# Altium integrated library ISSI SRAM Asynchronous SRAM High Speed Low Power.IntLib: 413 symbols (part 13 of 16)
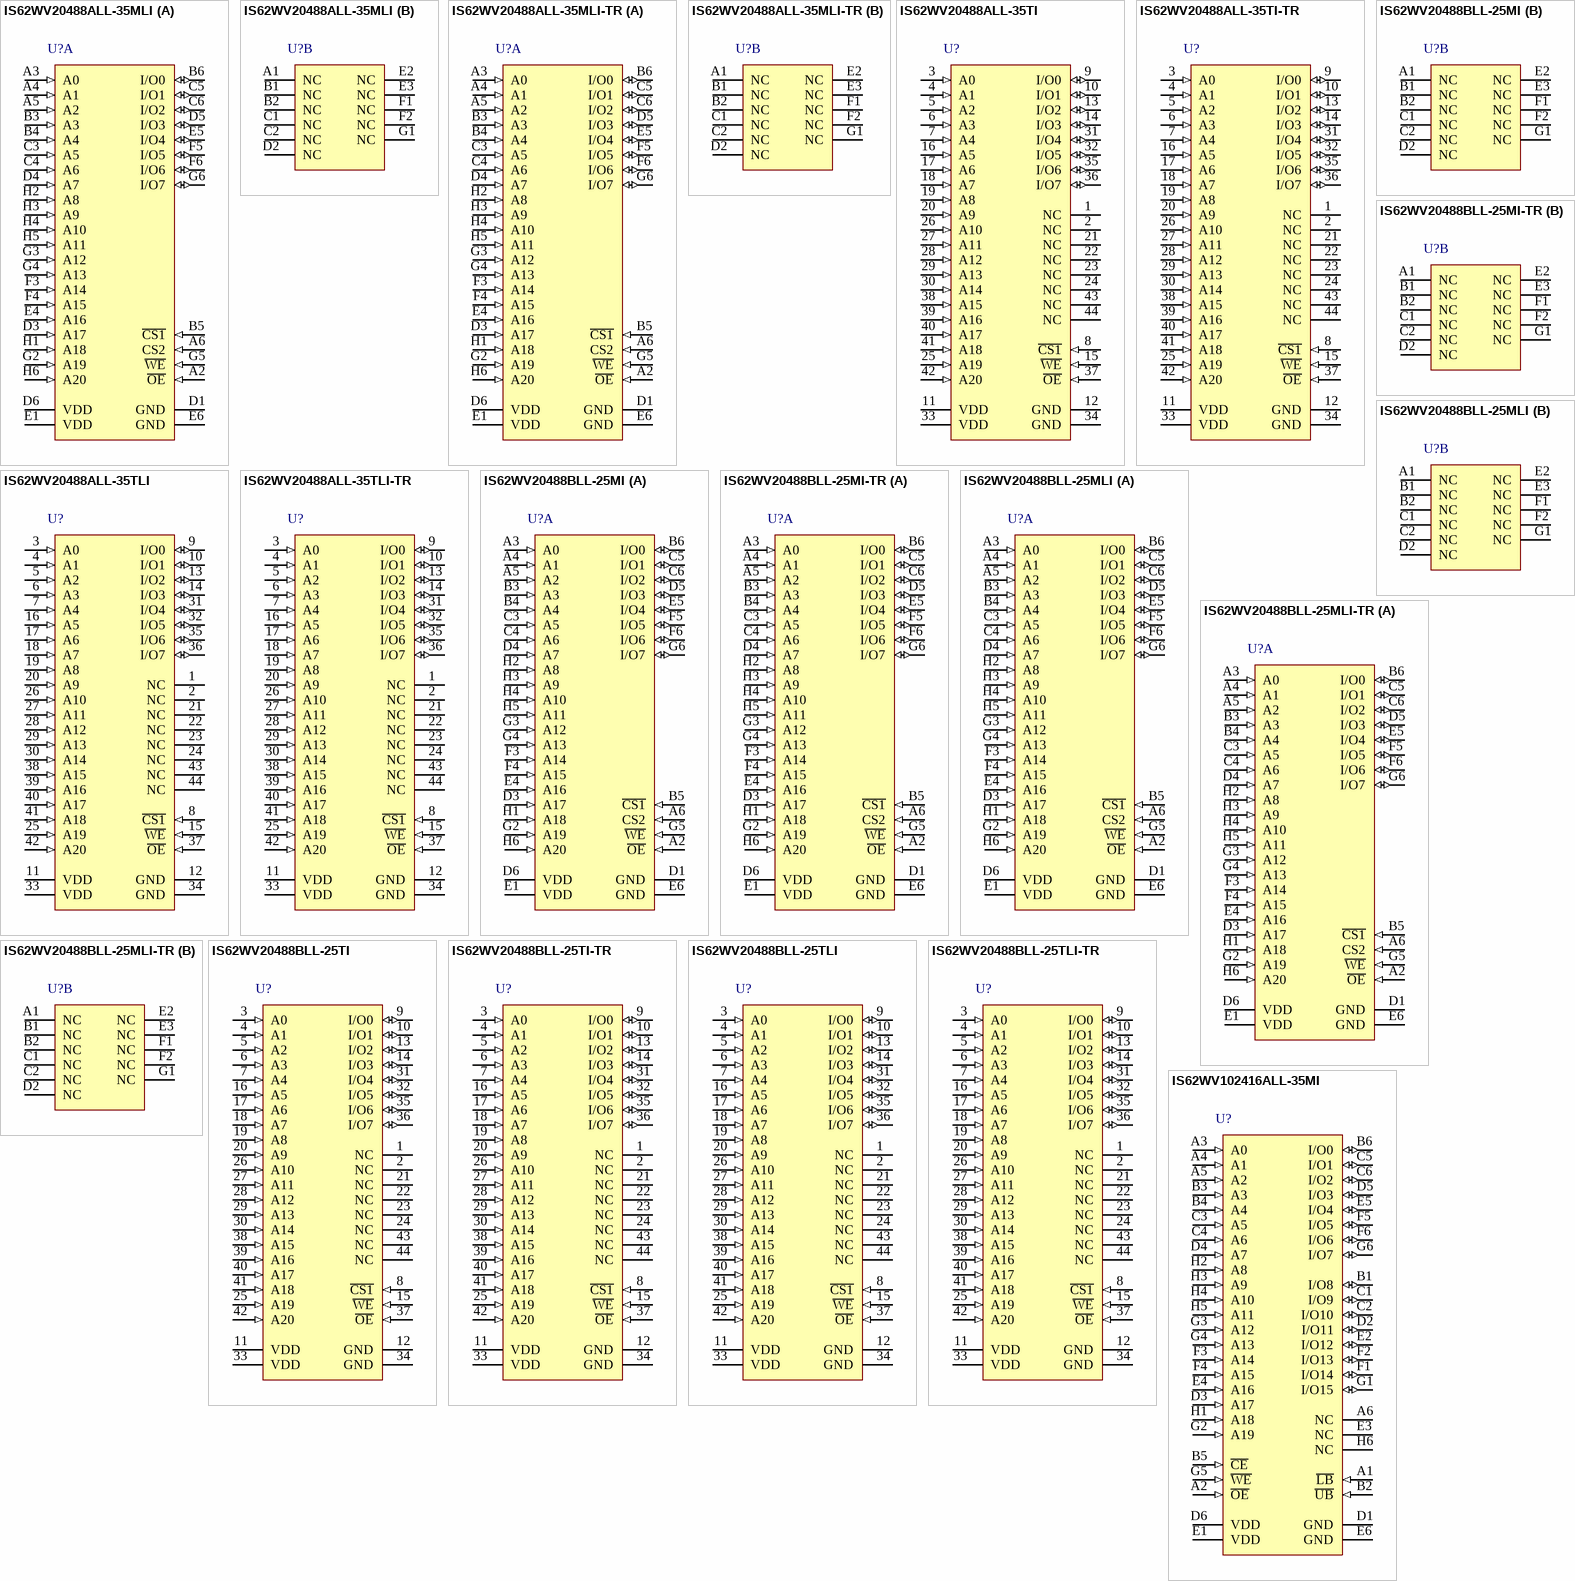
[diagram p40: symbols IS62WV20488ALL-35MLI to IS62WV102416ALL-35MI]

## IS62WV20488BLL-25MLI-TR
designator U?
16 M High Speed Low Power CMOS SRAM, 2 M x 8, -40 to 85 degC, 48-Pin BGA (TF-BGA-48), Pb-Free; Manufacturer: Integrated Silicon Solution Inc (ISSI); PartNumber: IS62WV20488BLL-25MLI-TR; Density: 16M; Organization: 2M x 8; Packing: Tape & Reel; Speed (ns): 25
footprint ISSI-TF-BGA-48-9000x11000DE (BGA, 48-Balls, Body 11x9mm, Pitch 0.75mm)
part A pins: A2 ~{OE} (in) "Output Enable Input", A3 A0 (in) "Address Input", A4 A1 (in) "Address Input", A5 A2 (in) "Address Input", A6 CS2 (in) "Chip Enable Input", B3 A3 (in) "Address Input", B4 A4 (in) "Address Input", B5 ~{CS1} (in) "Chip Enable Input", B6 I/O0 (io) "Data Input / Output", C3 A5 (in) "Address Input", C4 A6 (in) "Address Input", C5 I/O1 (io) "Data Input / Output", C6 I/O2 (io) "Data Input / Output", D1 GND (power) "Ground", D3 A17 (in) "Address Input", D4 A7 (in) "Address Input", D5 I/O3 (io) "Data Input / Output", D6 VDD (power) "Power", E1 VDD (power) "Power", E4 A16 (in) "Address Input", E5 I/O4 (io) "Data Input / Output", E6 GND (power) "Ground", F3 A14 (in) "Address Input", F4 A15 (in) "Address Input", F5 I/O5 (io) "Data Input / Output", F6 I/O6 (io) "Data Input / Output", G2 A19 (in) "Address Input", G3 A12 (in) "Address Input", G4 A13 (in) "Address Input", G5 ~{WE} (in) "Write Enable Input", G6 I/O7 (io) "Data Input / Output", H1 A18 (in) "Address Input", H2 A8 (in) "Address Input", H3 A9 (in) "Address Input", H4 A10 (in) "Address Input", H5 A11 (in) "Address Input", H6 A20 (in) "Address Input"
part B pins: A1 NC "No Connection", B1 NC "No Connection", B2 NC "No Connection", C1 NC "No Connection", C2 NC "No Connection", D2 NC "No Connection", E2 NC "No Connection", E3 NC "No Connection", F1 NC "No Connection", F2 NC "No Connection", G1 NC "No Connection"

## IS62WV20488BLL-25TI
designator U?
16 M High Speed Low Power CMOS SRAM, 2 M x 8, -40 to 85 degC, 44-Pin SOP (TSOP-2-44); Manufacturer: Integrated Silicon Solution Inc (ISSI); PartNumber: IS62WV20488BLL-25TI; Density: 16M; Organization: 2M x 8; Packing: Tray / Tube; Speed (ns): 25
footprint ISSI-TSOP-2-44_N (SOP, 44-Leads, Body 18.5x10.3mm, Pitch 0.8mm, IPC Medium Density)
pins: 1 NC "No Connection", 2 NC "No Connection", 3 A0 (in) "Address Inputs", 4 A1 (in) "Address Inputs", 5 A2 (in) "Address Inputs", 6 A3 (in) "Address Inputs", 7 A4 (in) "Address Inputs", 8 ~{CS1} (in) "Chip Enable Input", 9 I/O0 (io) "Data Input / Output", 10 I/O1 (io) "Data Input / Output", 11 VDD (power) "Power", 12 GND (power) "Ground", 13 I/O2 (io) "Data Input / Output", 14 I/O3 (io) "Data Input / Output", 15 ~{WE} (in) "Write Enable Input", 16 A5 (in) "Address Inputs", 17 A6 (in) "Address Inputs", 18 A7 (in) "Address Inputs", 19 A8 (in) "Address Inputs", 20 A9 (in) "Address Inputs", 21 NC "No Connection", 22 NC "No Connection", 23 NC "No Connection", 24 NC "No Connection", 25 A19 (in) "Address Inputs", 26 A10 (in) "Address Inputs", 27 A11 (in) "Address Inputs", 28 A12 (in) "Address Inputs", 29 A13 (in) "Address Inputs", 30 A14 (in) "Address Inputs", 31 I/O4 (io) "Data Input / Output", 32 I/O5 (io) "Data Input / Output", 33 VDD (power) "Power", 34 GND (power) "Ground", 35 I/O6 (io) "Data Input / Output", 36 I/O7 (io) "Data Input / Output", 37 ~{OE} (in) "Output Enable Input", 38 A15 (in) "Address Inputs", 39 A16 (in) "Address Inputs", 40 A17 (in) "Address Inputs", 41 A18 (in) "Address Inputs", 42 A20 (in) "Address Inputs", 43 NC "No Connection", 44 NC "No Connection"

## IS62WV20488BLL-25TI-TR
designator U?
16 M High Speed Low Power CMOS SRAM, 2 M x 8, -40 to 85 degC, 44-Pin SOP (TSOP-2-44); Manufacturer: Integrated Silicon Solution Inc (ISSI); PartNumber: IS62WV20488BLL-25TI-TR; Density: 16M; Organization: 2M x 8; Packing: Tape & Reel; Speed (ns): 25
footprint ISSI-TSOP-2-44_N (SOP, 44-Leads, Body 18.5x10.3mm, Pitch 0.8mm, IPC Medium Density)
pins: 1 NC "No Connection", 2 NC "No Connection", 3 A0 (in) "Address Inputs", 4 A1 (in) "Address Inputs", 5 A2 (in) "Address Inputs", 6 A3 (in) "Address Inputs", 7 A4 (in) "Address Inputs", 8 ~{CS1} (in) "Chip Enable Input", 9 I/O0 (io) "Data Input / Output", 10 I/O1 (io) "Data Input / Output", 11 VDD (power) "Power", 12 GND (power) "Ground", 13 I/O2 (io) "Data Input / Output", 14 I/O3 (io) "Data Input / Output", 15 ~{WE} (in) "Write Enable Input", 16 A5 (in) "Address Inputs", 17 A6 (in) "Address Inputs", 18 A7 (in) "Address Inputs", 19 A8 (in) "Address Inputs", 20 A9 (in) "Address Inputs", 21 NC "No Connection", 22 NC "No Connection", 23 NC "No Connection", 24 NC "No Connection", 25 A19 (in) "Address Inputs", 26 A10 (in) "Address Inputs", 27 A11 (in) "Address Inputs", 28 A12 (in) "Address Inputs", 29 A13 (in) "Address Inputs", 30 A14 (in) "Address Inputs", 31 I/O4 (io) "Data Input / Output", 32 I/O5 (io) "Data Input / Output", 33 VDD (power) "Power", 34 GND (power) "Ground", 35 I/O6 (io) "Data Input / Output", 36 I/O7 (io) "Data Input / Output", 37 ~{OE} (in) "Output Enable Input", 38 A15 (in) "Address Inputs", 39 A16 (in) "Address Inputs", 40 A17 (in) "Address Inputs", 41 A18 (in) "Address Inputs", 42 A20 (in) "Address Inputs", 43 NC "No Connection", 44 NC "No Connection"

## IS62WV20488BLL-25TLI
designator U?
16 M High Speed Low Power CMOS SRAM, 2 M x 8, -40 to 85 degC, 44-Pin SOP (TSOP-2-44), Pb-Free; Manufacturer: Integrated Silicon Solution Inc (ISSI); PartNumber: IS62WV20488BLL-25TLI; Density: 16M; Organization: 2M x 8; Packing: Tray / Tube; Speed (ns): 25
footprint ISSI-TSOP-2-44_N (SOP, 44-Leads, Body 18.5x10.3mm, Pitch 0.8mm, IPC Medium Density)
pins: 1 NC "No Connection", 2 NC "No Connection", 3 A0 (in) "Address Inputs", 4 A1 (in) "Address Inputs", 5 A2 (in) "Address Inputs", 6 A3 (in) "Address Inputs", 7 A4 (in) "Address Inputs", 8 ~{CS1} (in) "Chip Enable Input", 9 I/O0 (io) "Data Input / Output", 10 I/O1 (io) "Data Input / Output", 11 VDD (power) "Power", 12 GND (power) "Ground", 13 I/O2 (io) "Data Input / Output", 14 I/O3 (io) "Data Input / Output", 15 ~{WE} (in) "Write Enable Input", 16 A5 (in) "Address Inputs", 17 A6 (in) "Address Inputs", 18 A7 (in) "Address Inputs", 19 A8 (in) "Address Inputs", 20 A9 (in) "Address Inputs", 21 NC "No Connection", 22 NC "No Connection", 23 NC "No Connection", 24 NC "No Connection", 25 A19 (in) "Address Inputs", 26 A10 (in) "Address Inputs", 27 A11 (in) "Address Inputs", 28 A12 (in) "Address Inputs", 29 A13 (in) "Address Inputs", 30 A14 (in) "Address Inputs", 31 I/O4 (io) "Data Input / Output", 32 I/O5 (io) "Data Input / Output", 33 VDD (power) "Power", 34 GND (power) "Ground", 35 I/O6 (io) "Data Input / Output", 36 I/O7 (io) "Data Input / Output", 37 ~{OE} (in) "Output Enable Input", 38 A15 (in) "Address Inputs", 39 A16 (in) "Address Inputs", 40 A17 (in) "Address Inputs", 41 A18 (in) "Address Inputs", 42 A20 (in) "Address Inputs", 43 NC "No Connection", 44 NC "No Connection"

## IS62WV20488BLL-25TLI-TR
designator U?
16 M High Speed Low Power CMOS SRAM, 2 M x 8, -40 to 85 degC, 44-Pin SOP (TSOP-2-44), Pb-Free; Manufacturer: Integrated Silicon Solution Inc (ISSI); PartNumber: IS62WV20488BLL-25TLI-TR; Density: 16M; Organization: 2M x 8; Packing: Tape & Reel; Speed (ns): 25
footprint ISSI-TSOP-2-44_N (SOP, 44-Leads, Body 18.5x10.3mm, Pitch 0.8mm, IPC Medium Density)
pins: 1 NC "No Connection", 2 NC "No Connection", 3 A0 (in) "Address Inputs", 4 A1 (in) "Address Inputs", 5 A2 (in) "Address Inputs", 6 A3 (in) "Address Inputs", 7 A4 (in) "Address Inputs", 8 ~{CS1} (in) "Chip Enable Input", 9 I/O0 (io) "Data Input / Output", 10 I/O1 (io) "Data Input / Output", 11 VDD (power) "Power", 12 GND (power) "Ground", 13 I/O2 (io) "Data Input / Output", 14 I/O3 (io) "Data Input / Output", 15 ~{WE} (in) "Write Enable Input", 16 A5 (in) "Address Inputs", 17 A6 (in) "Address Inputs", 18 A7 (in) "Address Inputs", 19 A8 (in) "Address Inputs", 20 A9 (in) "Address Inputs", 21 NC "No Connection", 22 NC "No Connection", 23 NC "No Connection", 24 NC "No Connection", 25 A19 (in) "Address Inputs", 26 A10 (in) "Address Inputs", 27 A11 (in) "Address Inputs", 28 A12 (in) "Address Inputs", 29 A13 (in) "Address Inputs", 30 A14 (in) "Address Inputs", 31 I/O4 (io) "Data Input / Output", 32 I/O5 (io) "Data Input / Output", 33 VDD (power) "Power", 34 GND (power) "Ground", 35 I/O6 (io) "Data Input / Output", 36 I/O7 (io) "Data Input / Output", 37 ~{OE} (in) "Output Enable Input", 38 A15 (in) "Address Inputs", 39 A16 (in) "Address Inputs", 40 A17 (in) "Address Inputs", 41 A18 (in) "Address Inputs", 42 A20 (in) "Address Inputs", 43 NC "No Connection", 44 NC "No Connection"

## IS62WV102416ALL-35MI
designator U?
16 M High Speed Low Power Asynchronous CMOS SRAM, 1 M x 16, -40 to 85 degC, 48-Pin BGA (TF-BGA-48); Manufacturer: Integrated Silicon Solution Inc (ISSI); PartNumber: IS62WV102416ALL-35MI; Density: 16M; Organization: 1M x 16; Packing: Tray / Tube; Speed (ns): 35
footprint ISSI-TF-BGA-48-9000x11000DE (BGA, 48-Balls, Body 11x9mm, Pitch 0.75mm)
pins: A1 ~{LB} (in) "Lower-byte Control (I/O0-I/O7)", A2 ~{OE} (in) "Output Enable Input", A3 A0 (in) "Address Input", A4 A1 (in) "Address Input", A5 A2 (in) "Address Input", A6 NC "No Connection", B1 I/O8 (io) "Data Inputs/Output", B2 ~{UB} (in) "Upper-byte Control (I/O8-I/O15)", B3 A3 (in) "Address Input", B4 A4 (in) "Address Input", B5 ~{CE} (in) "Chip Enable Input", B6 I/O0 (io) "Data Inputs/Output", C1 I/O9 (io) "Data Inputs/Output", C2 I/O10 (io) "Data Inputs/Output", C3 A5 (in) "Address Input", C4 A6 (in) "Address Input", C5 I/O1 (io) "Data Inputs/Output", C6 I/O2 (io) "Data Inputs/Output", D1 GND (power) "Ground", D2 I/O11 (io) "Data Inputs/Output", D3 A17 (in) "Address Input", D4 A7 (in) "Address Input", D5 I/O3 (io) "Data Inputs/Output", D6 VDD (power) "Power", E1 VDD (power) "Power", E2 I/O12 (io) "Data Inputs/Output", E3 NC "No Connection", E4 A16 (in) "Address Input", E5 I/O4 (io) "Data Inputs/Output", E6 GND (power) "Ground", F1 I/O14 (io) "Data Inputs/Output", F2 I/O13 (io) "Data Inputs/Output", F3 A14 (in) "Address Input", F4 A15 (in) "Address Input", F5 I/O5 (io) "Data Inputs/Output", F6 I/O6 (io) "Data Inputs/Output", G1 I/O15 (io) "Data Inputs/Output", G2 A19 (in) "Address Input", G3 A12 (in) "Address Input", G4 A13 (in) "Address Input", G5 ~{WE} (in) "Write Enable Input", G6 I/O7 (io) "Data Inputs/Output", H1 A18 (in) "Address Input", H2 A8 (in) "Address Input", H3 A9 (in) "Address Input", H4 A10 (in) "Address Input", H5 A11 (in) "Address Input", H6 NC "No Connection"

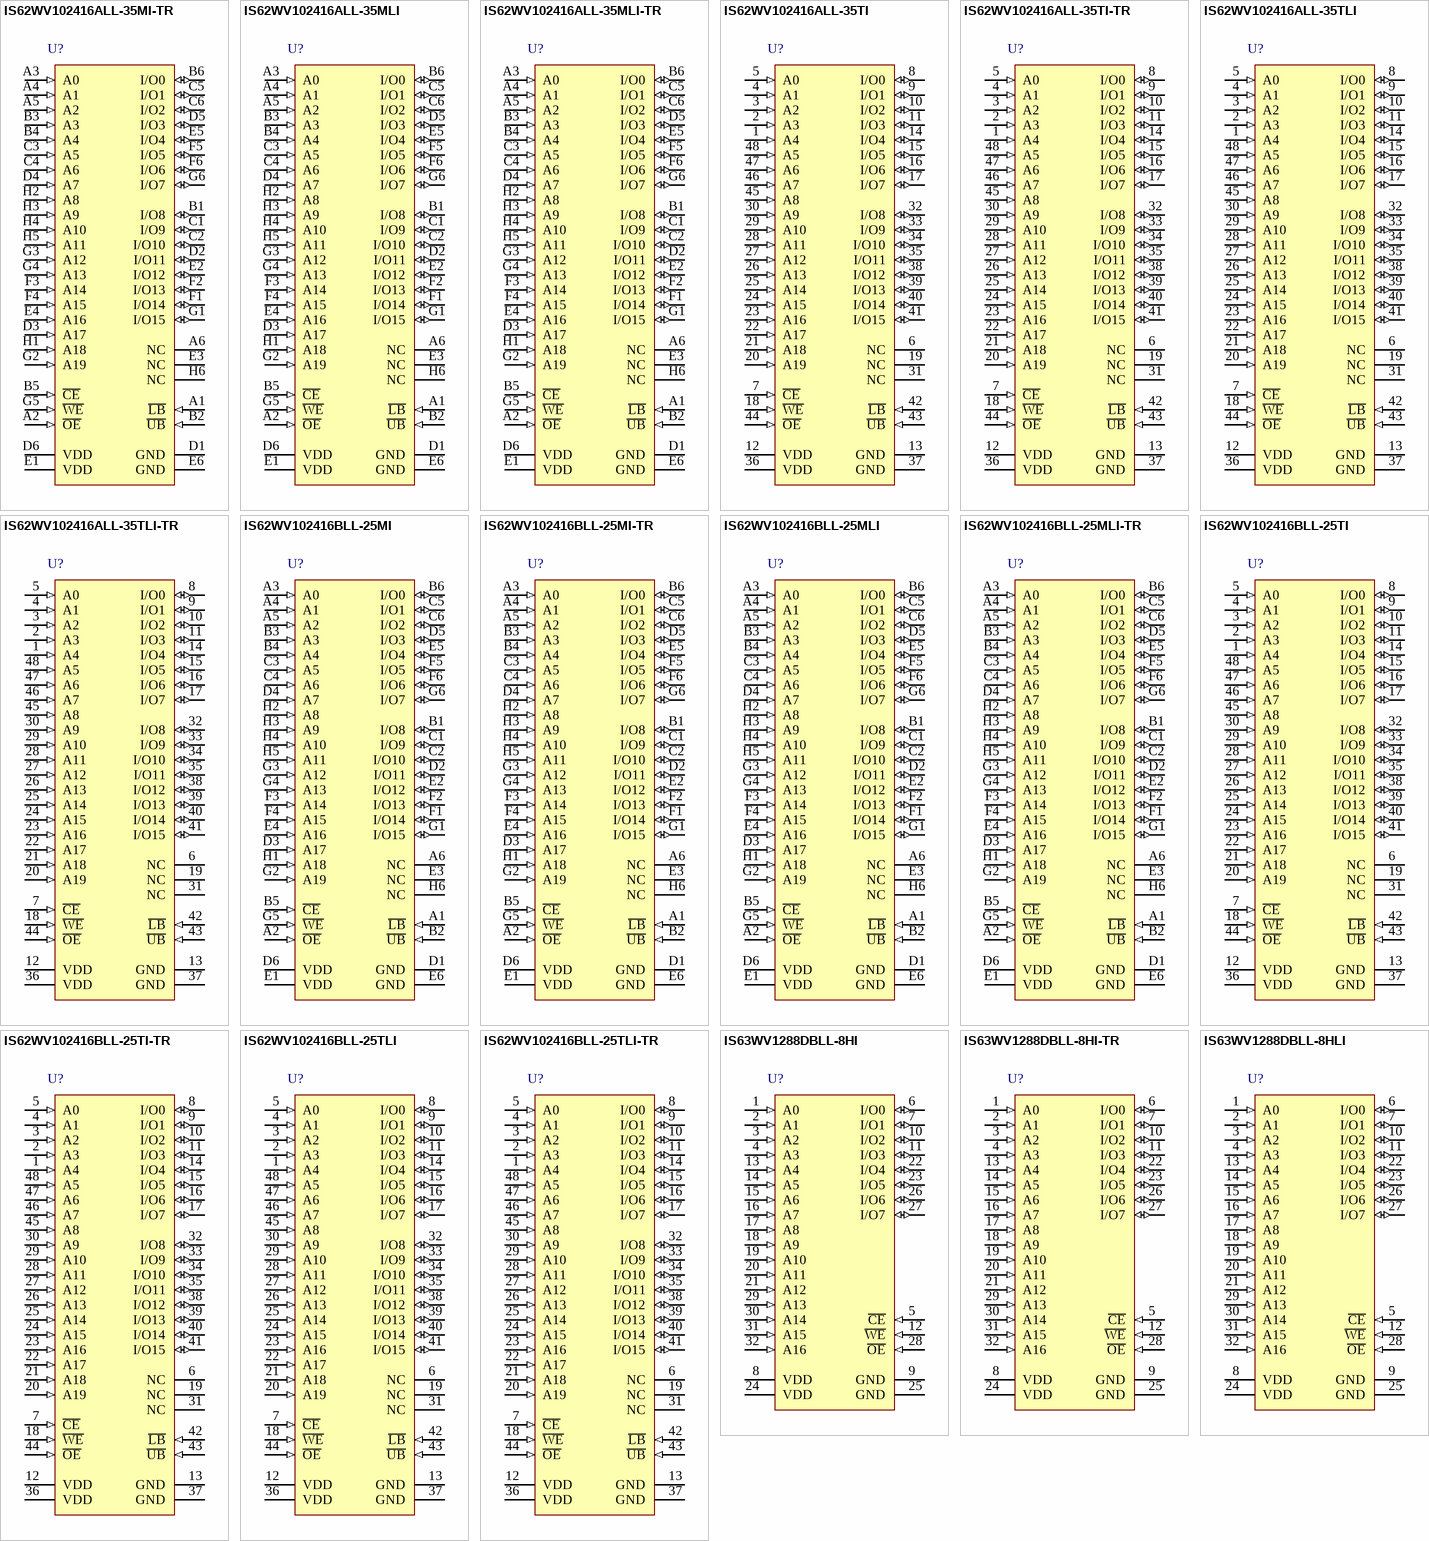
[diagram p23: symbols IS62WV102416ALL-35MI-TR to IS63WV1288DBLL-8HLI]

## IS62WV102416ALL-35MI-TR
designator U?
16 M High Speed Low Power Asynchronous CMOS SRAM, 1 M x 16, -40 to 85 degC, 48-Pin BGA (TF-BGA-48); Manufacturer: Integrated Silicon Solution Inc (ISSI); PartNumber: IS62WV102416ALL-35MI-TR; Density: 16M; Organization: 1M x 16; Packing: Tape & Reel; Speed (ns): 35
footprint ISSI-TF-BGA-48-9000x11000DE (BGA, 48-Balls, Body 11x9mm, Pitch 0.75mm)
pins: A1 ~{LB} (in) "Lower-byte Control (I/O0-I/O7)", A2 ~{OE} (in) "Output Enable Input", A3 A0 (in) "Address Input", A4 A1 (in) "Address Input", A5 A2 (in) "Address Input", A6 NC "No Connection", B1 I/O8 (io) "Data Inputs/Output", B2 ~{UB} (in) "Upper-byte Control (I/O8-I/O15)", B3 A3 (in) "Address Input", B4 A4 (in) "Address Input", B5 ~{CE} (in) "Chip Enable Input", B6 I/O0 (io) "Data Inputs/Output", C1 I/O9 (io) "Data Inputs/Output", C2 I/O10 (io) "Data Inputs/Output", C3 A5 (in) "Address Input", C4 A6 (in) "Address Input", C5 I/O1 (io) "Data Inputs/Output", C6 I/O2 (io) "Data Inputs/Output", D1 GND (power) "Ground", D2 I/O11 (io) "Data Inputs/Output", D3 A17 (in) "Address Input", D4 A7 (in) "Address Input", D5 I/O3 (io) "Data Inputs/Output", D6 VDD (power) "Power", E1 VDD (power) "Power", E2 I/O12 (io) "Data Inputs/Output", E3 NC "No Connection", E4 A16 (in) "Address Input", E5 I/O4 (io) "Data Inputs/Output", E6 GND (power) "Ground", F1 I/O14 (io) "Data Inputs/Output", F2 I/O13 (io) "Data Inputs/Output", F3 A14 (in) "Address Input", F4 A15 (in) "Address Input", F5 I/O5 (io) "Data Inputs/Output", F6 I/O6 (io) "Data Inputs/Output", G1 I/O15 (io) "Data Inputs/Output", G2 A19 (in) "Address Input", G3 A12 (in) "Address Input", G4 A13 (in) "Address Input", G5 ~{WE} (in) "Write Enable Input", G6 I/O7 (io) "Data Inputs/Output", H1 A18 (in) "Address Input", H2 A8 (in) "Address Input", H3 A9 (in) "Address Input", H4 A10 (in) "Address Input", H5 A11 (in) "Address Input", H6 NC "No Connection"

## IS62WV102416ALL-35MLI
designator U?
16 M High Speed Low Power Asynchronous CMOS SRAM, 1 M x 16, -40 to 85 degC, 48-Pin BGA (TF-BGA-48), Pb-Free; Manufacturer: Integrated Silicon Solution Inc (ISSI); PartNumber: IS62WV102416ALL-35MLI; Density: 16M; Organization: 1M x 16; Packing: Tray / Tube; Speed (ns): 35
footprint ISSI-TF-BGA-48-9000x11000DE (BGA, 48-Balls, Body 11x9mm, Pitch 0.75mm)
pins: A1 ~{LB} (in) "Lower-byte Control (I/O0-I/O7)", A2 ~{OE} (in) "Output Enable Input", A3 A0 (in) "Address Input", A4 A1 (in) "Address Input", A5 A2 (in) "Address Input", A6 NC "No Connection", B1 I/O8 (io) "Data Inputs/Output", B2 ~{UB} (in) "Upper-byte Control (I/O8-I/O15)", B3 A3 (in) "Address Input", B4 A4 (in) "Address Input", B5 ~{CE} (in) "Chip Enable Input", B6 I/O0 (io) "Data Inputs/Output", C1 I/O9 (io) "Data Inputs/Output", C2 I/O10 (io) "Data Inputs/Output", C3 A5 (in) "Address Input", C4 A6 (in) "Address Input", C5 I/O1 (io) "Data Inputs/Output", C6 I/O2 (io) "Data Inputs/Output", D1 GND (power) "Ground", D2 I/O11 (io) "Data Inputs/Output", D3 A17 (in) "Address Input", D4 A7 (in) "Address Input", D5 I/O3 (io) "Data Inputs/Output", D6 VDD (power) "Power", E1 VDD (power) "Power", E2 I/O12 (io) "Data Inputs/Output", E3 NC "No Connection", E4 A16 (in) "Address Input", E5 I/O4 (io) "Data Inputs/Output", E6 GND (power) "Ground", F1 I/O14 (io) "Data Inputs/Output", F2 I/O13 (io) "Data Inputs/Output", F3 A14 (in) "Address Input", F4 A15 (in) "Address Input", F5 I/O5 (io) "Data Inputs/Output", F6 I/O6 (io) "Data Inputs/Output", G1 I/O15 (io) "Data Inputs/Output", G2 A19 (in) "Address Input", G3 A12 (in) "Address Input", G4 A13 (in) "Address Input", G5 ~{WE} (in) "Write Enable Input", G6 I/O7 (io) "Data Inputs/Output", H1 A18 (in) "Address Input", H2 A8 (in) "Address Input", H3 A9 (in) "Address Input", H4 A10 (in) "Address Input", H5 A11 (in) "Address Input", H6 NC "No Connection"

## IS62WV102416ALL-35MLI-TR
designator U?
16 M High Speed Low Power Asynchronous CMOS SRAM, 1 M x 16, -40 to 85 degC, 48-Pin BGA (TF-BGA-48), Pb-Free; Manufacturer: Integrated Silicon Solution Inc (ISSI); PartNumber: IS62WV102416ALL-35MLI-TR; Density: 16M; Organization: 1M x 16; Packing: Tape & Reel; Speed (ns): 35
footprint ISSI-TF-BGA-48-9000x11000DE (BGA, 48-Balls, Body 11x9mm, Pitch 0.75mm)
pins: A1 ~{LB} (in) "Lower-byte Control (I/O0-I/O7)", A2 ~{OE} (in) "Output Enable Input", A3 A0 (in) "Address Input", A4 A1 (in) "Address Input", A5 A2 (in) "Address Input", A6 NC "No Connection", B1 I/O8 (io) "Data Inputs/Output", B2 ~{UB} (in) "Upper-byte Control (I/O8-I/O15)", B3 A3 (in) "Address Input", B4 A4 (in) "Address Input", B5 ~{CE} (in) "Chip Enable Input", B6 I/O0 (io) "Data Inputs/Output", C1 I/O9 (io) "Data Inputs/Output", C2 I/O10 (io) "Data Inputs/Output", C3 A5 (in) "Address Input", C4 A6 (in) "Address Input", C5 I/O1 (io) "Data Inputs/Output", C6 I/O2 (io) "Data Inputs/Output", D1 GND (power) "Ground", D2 I/O11 (io) "Data Inputs/Output", D3 A17 (in) "Address Input", D4 A7 (in) "Address Input", D5 I/O3 (io) "Data Inputs/Output", D6 VDD (power) "Power", E1 VDD (power) "Power", E2 I/O12 (io) "Data Inputs/Output", E3 NC "No Connection", E4 A16 (in) "Address Input", E5 I/O4 (io) "Data Inputs/Output", E6 GND (power) "Ground", F1 I/O14 (io) "Data Inputs/Output", F2 I/O13 (io) "Data Inputs/Output", F3 A14 (in) "Address Input", F4 A15 (in) "Address Input", F5 I/O5 (io) "Data Inputs/Output", F6 I/O6 (io) "Data Inputs/Output", G1 I/O15 (io) "Data Inputs/Output", G2 A19 (in) "Address Input", G3 A12 (in) "Address Input", G4 A13 (in) "Address Input", G5 ~{WE} (in) "Write Enable Input", G6 I/O7 (io) "Data Inputs/Output", H1 A18 (in) "Address Input", H2 A8 (in) "Address Input", H3 A9 (in) "Address Input", H4 A10 (in) "Address Input", H5 A11 (in) "Address Input", H6 NC "No Connection"

## IS62WV102416ALL-35TI
designator U?
16 M High Speed Low Power Asynchronous CMOS SRAM, 1 M x 16, -40 to 85 degC, 48-Pin SOP (TSOP-1-48); Manufacturer: Integrated Silicon Solution Inc (ISSI); PartNumber: IS62WV102416ALL-35TI; Density: 16M; Organization: 1M x 16; Packing: Tray / Tube; Speed (ns): 35
footprint ISSI-TSOP-1-48-12000X20000DE_N (SOP, 48-Leads, Body 18.6x12.2mm, Pitch 0.5mm, IPC Medium Density)
pins: 1 A4 (in) "Address Input", 2 A3 (in) "Address Input", 3 A2 (in) "Address Input", 4 A1 (in) "Address Input", 5 A0 (in) "Address Input", 6 NC "No Connection", 7 ~{CE} (in) "Chip Enable Input", 8 I/O0 (io) "Data Input/Output", 9 I/O1 (io) "Data Input/Output", 10 I/O2 (io) "Data Input/Output", 11 I/O3 (io) "Data Input/Output", 12 VDD (power) "Power", 13 GND (power) "Ground", 14 I/O4 (io) "Data Input/Output", 15 I/O5 (io) "Data Input/Output", 16 I/O6 (io) "Data Input/Output", 17 I/O7 (io) "Data Input/Output", 18 ~{WE} (in) "Write Enable Input", 19 NC "No Connection", 20 A19 (in) "Address Input", 21 A18 (in) "Address Input", 22 A17 (in) "Address Input", 23 A16 (in) "Address Input", 24 A15 (in) "Address Input", 25 A14 (in) "Address Input", 26 A13 (in) "Address Input", 27 A12 (in) "Address Input", 28 A11 (in) "Address Input", 29 A10 (in) "Address Input", 30 A9 (in) "Address Input", 31 NC "No Connection", 32 I/O8 (io) "Data Input/Output", 33 I/O9 (io) "Data Input/Output", 34 I/O10 (io) "Data Input/Output", 35 I/O11 (io) "Data Input/Output", 36 VDD (power) "Power", 37 GND (power) "Ground", 38 I/O12 (io) "Data Input/Output", 39 I/O13 (io) "Data Input/Output", 40 I/O14 (io) "Data Input/Output", 41 I/O15 (io) "Data Input/Output", 42 ~{LB} (in) "Lower-byte Control (I/O0-I/O7)", 43 ~{UB} (in) "Upper-byte Control (I/O8-I/O15)", 44 ~{OE} (in) "Output Enable Input", 45 A8 (in) "Address Input", 46 A7 (in) "Address Input", 47 A6 (in) "Address Input", 48 A5 (in) "Address Input"

## IS62WV102416ALL-35TI-TR
designator U?
16 M High Speed Low Power Asynchronous CMOS SRAM, 1 M x 16, -40 to 85 degC, 48-Pin SOP (TSOP-1-48); Manufacturer: Integrated Silicon Solution Inc (ISSI); PartNumber: IS62WV102416ALL-35TI-TR; Density: 16M; Organization: 1M x 16; Packing: Tape & Reel; Speed (ns): 35
footprint ISSI-TSOP-1-48-12000X20000DE_N (SOP, 48-Leads, Body 18.6x12.2mm, Pitch 0.5mm, IPC Medium Density)
pins: 1 A4 (in) "Address Input", 2 A3 (in) "Address Input", 3 A2 (in) "Address Input", 4 A1 (in) "Address Input", 5 A0 (in) "Address Input", 6 NC "No Connection", 7 ~{CE} (in) "Chip Enable Input", 8 I/O0 (io) "Data Input/Output", 9 I/O1 (io) "Data Input/Output", 10 I/O2 (io) "Data Input/Output", 11 I/O3 (io) "Data Input/Output", 12 VDD (power) "Power", 13 GND (power) "Ground", 14 I/O4 (io) "Data Input/Output", 15 I/O5 (io) "Data Input/Output", 16 I/O6 (io) "Data Input/Output", 17 I/O7 (io) "Data Input/Output", 18 ~{WE} (in) "Write Enable Input", 19 NC "No Connection", 20 A19 (in) "Address Input", 21 A18 (in) "Address Input", 22 A17 (in) "Address Input", 23 A16 (in) "Address Input", 24 A15 (in) "Address Input", 25 A14 (in) "Address Input", 26 A13 (in) "Address Input", 27 A12 (in) "Address Input", 28 A11 (in) "Address Input", 29 A10 (in) "Address Input", 30 A9 (in) "Address Input", 31 NC "No Connection", 32 I/O8 (io) "Data Input/Output", 33 I/O9 (io) "Data Input/Output", 34 I/O10 (io) "Data Input/Output", 35 I/O11 (io) "Data Input/Output", 36 VDD (power) "Power", 37 GND (power) "Ground", 38 I/O12 (io) "Data Input/Output", 39 I/O13 (io) "Data Input/Output", 40 I/O14 (io) "Data Input/Output", 41 I/O15 (io) "Data Input/Output", 42 ~{LB} (in) "Lower-byte Control (I/O0-I/O7)", 43 ~{UB} (in) "Upper-byte Control (I/O8-I/O15)", 44 ~{OE} (in) "Output Enable Input", 45 A8 (in) "Address Input", 46 A7 (in) "Address Input", 47 A6 (in) "Address Input", 48 A5 (in) "Address Input"

## IS62WV102416ALL-35TLI
designator U?
16 M High Speed Low Power Asynchronous CMOS SRAM, 1 M x 16, -40 to 85 degC, 48-Pin SOP (TSOP-1-48), Pb-Free; Manufacturer: Integrated Silicon Solution Inc (ISSI); PartNumber: IS62WV102416ALL-35TLI; Density: 16M; Organization: 1M x 16; Packing: Tray / Tube; Speed (ns): 35
footprint ISSI-TSOP-1-48-12000X20000DE_N (SOP, 48-Leads, Body 18.6x12.2mm, Pitch 0.5mm, IPC Medium Density)
pins: 1 A4 (in) "Address Input", 2 A3 (in) "Address Input", 3 A2 (in) "Address Input", 4 A1 (in) "Address Input", 5 A0 (in) "Address Input", 6 NC "No Connection", 7 ~{CE} (in) "Chip Enable Input", 8 I/O0 (io) "Data Input/Output", 9 I/O1 (io) "Data Input/Output", 10 I/O2 (io) "Data Input/Output", 11 I/O3 (io) "Data Input/Output", 12 VDD (power) "Power", 13 GND (power) "Ground", 14 I/O4 (io) "Data Input/Output", 15 I/O5 (io) "Data Input/Output", 16 I/O6 (io) "Data Input/Output", 17 I/O7 (io) "Data Input/Output", 18 ~{WE} (in) "Write Enable Input", 19 NC "No Connection", 20 A19 (in) "Address Input", 21 A18 (in) "Address Input", 22 A17 (in) "Address Input", 23 A16 (in) "Address Input", 24 A15 (in) "Address Input", 25 A14 (in) "Address Input", 26 A13 (in) "Address Input", 27 A12 (in) "Address Input", 28 A11 (in) "Address Input", 29 A10 (in) "Address Input", 30 A9 (in) "Address Input", 31 NC "No Connection", 32 I/O8 (io) "Data Input/Output", 33 I/O9 (io) "Data Input/Output", 34 I/O10 (io) "Data Input/Output", 35 I/O11 (io) "Data Input/Output", 36 VDD (power) "Power", 37 GND (power) "Ground", 38 I/O12 (io) "Data Input/Output", 39 I/O13 (io) "Data Input/Output", 40 I/O14 (io) "Data Input/Output", 41 I/O15 (io) "Data Input/Output", 42 ~{LB} (in) "Lower-byte Control (I/O0-I/O7)", 43 ~{UB} (in) "Upper-byte Control (I/O8-I/O15)", 44 ~{OE} (in) "Output Enable Input", 45 A8 (in) "Address Input", 46 A7 (in) "Address Input", 47 A6 (in) "Address Input", 48 A5 (in) "Address Input"

## IS62WV102416ALL-35TLI-TR
designator U?
16 M High Speed Low Power Asynchronous CMOS SRAM, 1 M x 16, -40 to 85 degC, 48-Pin SOP (TSOP-1-48), Pb-Free; Manufacturer: Integrated Silicon Solution Inc (ISSI); PartNumber: IS62WV102416ALL-35TLI-TR; Density: 16M; Organization: 1M x 16; Packing: Tape & Reel; Speed (ns): 35
footprint ISSI-TSOP-1-48-12000X20000DE_N (SOP, 48-Leads, Body 18.6x12.2mm, Pitch 0.5mm, IPC Medium Density)
pins: 1 A4 (in) "Address Input", 2 A3 (in) "Address Input", 3 A2 (in) "Address Input", 4 A1 (in) "Address Input", 5 A0 (in) "Address Input", 6 NC "No Connection", 7 ~{CE} (in) "Chip Enable Input", 8 I/O0 (io) "Data Input/Output", 9 I/O1 (io) "Data Input/Output", 10 I/O2 (io) "Data Input/Output", 11 I/O3 (io) "Data Input/Output", 12 VDD (power) "Power", 13 GND (power) "Ground", 14 I/O4 (io) "Data Input/Output", 15 I/O5 (io) "Data Input/Output", 16 I/O6 (io) "Data Input/Output", 17 I/O7 (io) "Data Input/Output", 18 ~{WE} (in) "Write Enable Input", 19 NC "No Connection", 20 A19 (in) "Address Input", 21 A18 (in) "Address Input", 22 A17 (in) "Address Input", 23 A16 (in) "Address Input", 24 A15 (in) "Address Input", 25 A14 (in) "Address Input", 26 A13 (in) "Address Input", 27 A12 (in) "Address Input", 28 A11 (in) "Address Input", 29 A10 (in) "Address Input", 30 A9 (in) "Address Input", 31 NC "No Connection", 32 I/O8 (io) "Data Input/Output", 33 I/O9 (io) "Data Input/Output", 34 I/O10 (io) "Data Input/Output", 35 I/O11 (io) "Data Input/Output", 36 VDD (power) "Power", 37 GND (power) "Ground", 38 I/O12 (io) "Data Input/Output", 39 I/O13 (io) "Data Input/Output", 40 I/O14 (io) "Data Input/Output", 41 I/O15 (io) "Data Input/Output", 42 ~{LB} (in) "Lower-byte Control (I/O0-I/O7)", 43 ~{UB} (in) "Upper-byte Control (I/O8-I/O15)", 44 ~{OE} (in) "Output Enable Input", 45 A8 (in) "Address Input", 46 A7 (in) "Address Input", 47 A6 (in) "Address Input", 48 A5 (in) "Address Input"

## IS62WV102416BLL-25MI
designator U?
16 M High Speed Low Power Asynchronous CMOS SRAM, 1 M x 16, -40 to 85 degC, 48-Pin BGA (TF-BGA-48); Manufacturer: Integrated Silicon Solution Inc (ISSI); PartNumber: IS62WV102416BLL-25MI; Density: 16M; Organization: 1M x 16; Packing: Tray / Tube; Speed (ns): 25
footprint ISSI-TF-BGA-48-9000x11000DE (BGA, 48-Balls, Body 11x9mm, Pitch 0.75mm)
pins: A1 ~{LB} (in) "Lower-byte Control (I/O0-I/O7)", A2 ~{OE} (in) "Output Enable Input", A3 A0 (in) "Address Input", A4 A1 (in) "Address Input", A5 A2 (in) "Address Input", A6 NC "No Connection", B1 I/O8 (io) "Data Inputs/Output", B2 ~{UB} (in) "Upper-byte Control (I/O8-I/O15)", B3 A3 (in) "Address Input", B4 A4 (in) "Address Input", B5 ~{CE} (in) "Chip Enable Input", B6 I/O0 (io) "Data Inputs/Output", C1 I/O9 (io) "Data Inputs/Output", C2 I/O10 (io) "Data Inputs/Output", C3 A5 (in) "Address Input", C4 A6 (in) "Address Input", C5 I/O1 (io) "Data Inputs/Output", C6 I/O2 (io) "Data Inputs/Output", D1 GND (power) "Ground", D2 I/O11 (io) "Data Inputs/Output", D3 A17 (in) "Address Input", D4 A7 (in) "Address Input", D5 I/O3 (io) "Data Inputs/Output", D6 VDD (power) "Power", E1 VDD (power) "Power", E2 I/O12 (io) "Data Inputs/Output", E3 NC "No Connection", E4 A16 (in) "Address Input", E5 I/O4 (io) "Data Inputs/Output", E6 GND (power) "Ground", F1 I/O14 (io) "Data Inputs/Output", F2 I/O13 (io) "Data Inputs/Output", F3 A14 (in) "Address Input", F4 A15 (in) "Address Input", F5 I/O5 (io) "Data Inputs/Output", F6 I/O6 (io) "Data Inputs/Output", G1 I/O15 (io) "Data Inputs/Output", G2 A19 (in) "Address Input", G3 A12 (in) "Address Input", G4 A13 (in) "Address Input", G5 ~{WE} (in) "Write Enable Input", G6 I/O7 (io) "Data Inputs/Output", H1 A18 (in) "Address Input", H2 A8 (in) "Address Input", H3 A9 (in) "Address Input", H4 A10 (in) "Address Input", H5 A11 (in) "Address Input", H6 NC "No Connection"

## IS62WV102416BLL-25MI-TR
designator U?
16 M High Speed Low Power Asynchronous CMOS SRAM, 1 M x 16, -40 to 85 degC, 48-Pin BGA (TF-BGA-48); Manufacturer: Integrated Silicon Solution Inc (ISSI); PartNumber: IS62WV102416BLL-25MI-TR; Density: 16M; Organization: 1M x 16; Packing: Tape & Reel; Speed (ns): 25
footprint ISSI-TF-BGA-48-9000x11000DE (BGA, 48-Balls, Body 11x9mm, Pitch 0.75mm)
pins: A1 ~{LB} (in) "Lower-byte Control (I/O0-I/O7)", A2 ~{OE} (in) "Output Enable Input", A3 A0 (in) "Address Input", A4 A1 (in) "Address Input", A5 A2 (in) "Address Input", A6 NC "No Connection", B1 I/O8 (io) "Data Inputs/Output", B2 ~{UB} (in) "Upper-byte Control (I/O8-I/O15)", B3 A3 (in) "Address Input", B4 A4 (in) "Address Input", B5 ~{CE} (in) "Chip Enable Input", B6 I/O0 (io) "Data Inputs/Output", C1 I/O9 (io) "Data Inputs/Output", C2 I/O10 (io) "Data Inputs/Output", C3 A5 (in) "Address Input", C4 A6 (in) "Address Input", C5 I/O1 (io) "Data Inputs/Output", C6 I/O2 (io) "Data Inputs/Output", D1 GND (power) "Ground", D2 I/O11 (io) "Data Inputs/Output", D3 A17 (in) "Address Input", D4 A7 (in) "Address Input", D5 I/O3 (io) "Data Inputs/Output", D6 VDD (power) "Power", E1 VDD (power) "Power", E2 I/O12 (io) "Data Inputs/Output", E3 NC "No Connection", E4 A16 (in) "Address Input", E5 I/O4 (io) "Data Inputs/Output", E6 GND (power) "Ground", F1 I/O14 (io) "Data Inputs/Output", F2 I/O13 (io) "Data Inputs/Output", F3 A14 (in) "Address Input", F4 A15 (in) "Address Input", F5 I/O5 (io) "Data Inputs/Output", F6 I/O6 (io) "Data Inputs/Output", G1 I/O15 (io) "Data Inputs/Output", G2 A19 (in) "Address Input", G3 A12 (in) "Address Input", G4 A13 (in) "Address Input", G5 ~{WE} (in) "Write Enable Input", G6 I/O7 (io) "Data Inputs/Output", H1 A18 (in) "Address Input", H2 A8 (in) "Address Input", H3 A9 (in) "Address Input", H4 A10 (in) "Address Input", H5 A11 (in) "Address Input", H6 NC "No Connection"

## IS62WV102416BLL-25MLI
designator U?
16 M High Speed Low Power Asynchronous CMOS SRAM, 1 M x 16, -40 to 85 degC, 48-Pin BGA (TF-BGA-48), Pb-Free; Manufacturer: Integrated Silicon Solution Inc (ISSI); PartNumber: IS62WV102416BLL-25MLI; Density: 16M; Organization: 1M x 16; Packing: Tray / Tube; Speed (ns): 25
footprint ISSI-TF-BGA-48-9000x11000DE (BGA, 48-Balls, Body 11x9mm, Pitch 0.75mm)
pins: A1 ~{LB} (in) "Lower-byte Control (I/O0-I/O7)", A2 ~{OE} (in) "Output Enable Input", A3 A0 (in) "Address Input", A4 A1 (in) "Address Input", A5 A2 (in) "Address Input", A6 NC "No Connection", B1 I/O8 (io) "Data Inputs/Output", B2 ~{UB} (in) "Upper-byte Control (I/O8-I/O15)", B3 A3 (in) "Address Input", B4 A4 (in) "Address Input", B5 ~{CE} (in) "Chip Enable Input", B6 I/O0 (io) "Data Inputs/Output", C1 I/O9 (io) "Data Inputs/Output", C2 I/O10 (io) "Data Inputs/Output", C3 A5 (in) "Address Input", C4 A6 (in) "Address Input", C5 I/O1 (io) "Data Inputs/Output", C6 I/O2 (io) "Data Inputs/Output", D1 GND (power) "Ground", D2 I/O11 (io) "Data Inputs/Output", D3 A17 (in) "Address Input", D4 A7 (in) "Address Input", D5 I/O3 (io) "Data Inputs/Output", D6 VDD (power) "Power", E1 VDD (power) "Power", E2 I/O12 (io) "Data Inputs/Output", E3 NC "No Connection", E4 A16 (in) "Address Input", E5 I/O4 (io) "Data Inputs/Output", E6 GND (power) "Ground", F1 I/O14 (io) "Data Inputs/Output", F2 I/O13 (io) "Data Inputs/Output", F3 A14 (in) "Address Input", F4 A15 (in) "Address Input", F5 I/O5 (io) "Data Inputs/Output", F6 I/O6 (io) "Data Inputs/Output", G1 I/O15 (io) "Data Inputs/Output", G2 A19 (in) "Address Input", G3 A12 (in) "Address Input", G4 A13 (in) "Address Input", G5 ~{WE} (in) "Write Enable Input", G6 I/O7 (io) "Data Inputs/Output", H1 A18 (in) "Address Input", H2 A8 (in) "Address Input", H3 A9 (in) "Address Input", H4 A10 (in) "Address Input", H5 A11 (in) "Address Input", H6 NC "No Connection"

## IS62WV102416BLL-25MLI-TR
designator U?
16 M High Speed Low Power Asynchronous CMOS SRAM, 1 M x 16, -40 to 85 degC, 48-Pin BGA (TF-BGA-48), Pb-Free; Manufacturer: Integrated Silicon Solution Inc (ISSI); PartNumber: IS62WV102416BLL-25MLI-TR; Density: 16M; Organization: 1M x 16; Packing: Tape & Reel; Speed (ns): 25
footprint ISSI-TF-BGA-48-9000x11000DE (BGA, 48-Balls, Body 11x9mm, Pitch 0.75mm)
pins: A1 ~{LB} (in) "Lower-byte Control (I/O0-I/O7)", A2 ~{OE} (in) "Output Enable Input", A3 A0 (in) "Address Input", A4 A1 (in) "Address Input", A5 A2 (in) "Address Input", A6 NC "No Connection", B1 I/O8 (io) "Data Inputs/Output", B2 ~{UB} (in) "Upper-byte Control (I/O8-I/O15)", B3 A3 (in) "Address Input", B4 A4 (in) "Address Input", B5 ~{CE} (in) "Chip Enable Input", B6 I/O0 (io) "Data Inputs/Output", C1 I/O9 (io) "Data Inputs/Output", C2 I/O10 (io) "Data Inputs/Output", C3 A5 (in) "Address Input", C4 A6 (in) "Address Input", C5 I/O1 (io) "Data Inputs/Output", C6 I/O2 (io) "Data Inputs/Output", D1 GND (power) "Ground", D2 I/O11 (io) "Data Inputs/Output", D3 A17 (in) "Address Input", D4 A7 (in) "Address Input", D5 I/O3 (io) "Data Inputs/Output", D6 VDD (power) "Power", E1 VDD (power) "Power", E2 I/O12 (io) "Data Inputs/Output", E3 NC "No Connection", E4 A16 (in) "Address Input", E5 I/O4 (io) "Data Inputs/Output", E6 GND (power) "Ground", F1 I/O14 (io) "Data Inputs/Output", F2 I/O13 (io) "Data Inputs/Output", F3 A14 (in) "Address Input", F4 A15 (in) "Address Input", F5 I/O5 (io) "Data Inputs/Output", F6 I/O6 (io) "Data Inputs/Output", G1 I/O15 (io) "Data Inputs/Output", G2 A19 (in) "Address Input", G3 A12 (in) "Address Input", G4 A13 (in) "Address Input", G5 ~{WE} (in) "Write Enable Input", G6 I/O7 (io) "Data Inputs/Output", H1 A18 (in) "Address Input", H2 A8 (in) "Address Input", H3 A9 (in) "Address Input", H4 A10 (in) "Address Input", H5 A11 (in) "Address Input", H6 NC "No Connection"

## IS62WV102416BLL-25TI
designator U?
16 M High Speed Low Power Asynchronous CMOS SRAM, 1 M x 16, -40 to 85 degC, 48-Pin SOP (TSOP-1-48); Manufacturer: Integrated Silicon Solution Inc (ISSI); PartNumber: IS62WV102416BLL-25TI; Density: 16M; Organization: 1M x 16; Packing: Tray / Tube; Speed (ns): 25
footprint ISSI-TSOP-1-48-12000X20000DE_N (SOP, 48-Leads, Body 18.6x12.2mm, Pitch 0.5mm, IPC Medium Density)
pins: 1 A4 (in) "Address Input", 2 A3 (in) "Address Input", 3 A2 (in) "Address Input", 4 A1 (in) "Address Input", 5 A0 (in) "Address Input", 6 NC "No Connection", 7 ~{CE} (in) "Chip Enable Input", 8 I/O0 (io) "Data Input/Output", 9 I/O1 (io) "Data Input/Output", 10 I/O2 (io) "Data Input/Output", 11 I/O3 (io) "Data Input/Output", 12 VDD (power) "Power", 13 GND (power) "Ground", 14 I/O4 (io) "Data Input/Output", 15 I/O5 (io) "Data Input/Output", 16 I/O6 (io) "Data Input/Output", 17 I/O7 (io) "Data Input/Output", 18 ~{WE} (in) "Write Enable Input", 19 NC "No Connection", 20 A19 (in) "Address Input", 21 A18 (in) "Address Input", 22 A17 (in) "Address Input", 23 A16 (in) "Address Input", 24 A15 (in) "Address Input", 25 A14 (in) "Address Input", 26 A13 (in) "Address Input", 27 A12 (in) "Address Input", 28 A11 (in) "Address Input", 29 A10 (in) "Address Input", 30 A9 (in) "Address Input", 31 NC "No Connection", 32 I/O8 (io) "Data Input/Output", 33 I/O9 (io) "Data Input/Output", 34 I/O10 (io) "Data Input/Output", 35 I/O11 (io) "Data Input/Output", 36 VDD (power) "Power", 37 GND (power) "Ground", 38 I/O12 (io) "Data Input/Output", 39 I/O13 (io) "Data Input/Output", 40 I/O14 (io) "Data Input/Output", 41 I/O15 (io) "Data Input/Output", 42 ~{LB} (in) "Lower-byte Control (I/O0-I/O7)", 43 ~{UB} (in) "Upper-byte Control (I/O8-I/O15)", 44 ~{OE} (in) "Output Enable Input", 45 A8 (in) "Address Input", 46 A7 (in) "Address Input", 47 A6 (in) "Address Input", 48 A5 (in) "Address Input"

## IS62WV102416BLL-25TI-TR
designator U?
16 M High Speed Low Power Asynchronous CMOS SRAM, 1 M x 16, -40 to 85 degC, 48-Pin SOP (TSOP-1-48); Manufacturer: Integrated Silicon Solution Inc (ISSI); PartNumber: IS62WV102416BLL-25TI-TR; Density: 16M; Organization: 1M x 16; Packing: Tape & Reel; Speed (ns): 25
footprint ISSI-TSOP-1-48-12000X20000DE_N (SOP, 48-Leads, Body 18.6x12.2mm, Pitch 0.5mm, IPC Medium Density)
pins: 1 A4 (in) "Address Input", 2 A3 (in) "Address Input", 3 A2 (in) "Address Input", 4 A1 (in) "Address Input", 5 A0 (in) "Address Input", 6 NC "No Connection", 7 ~{CE} (in) "Chip Enable Input", 8 I/O0 (io) "Data Input/Output", 9 I/O1 (io) "Data Input/Output", 10 I/O2 (io) "Data Input/Output", 11 I/O3 (io) "Data Input/Output", 12 VDD (power) "Power", 13 GND (power) "Ground", 14 I/O4 (io) "Data Input/Output", 15 I/O5 (io) "Data Input/Output", 16 I/O6 (io) "Data Input/Output", 17 I/O7 (io) "Data Input/Output", 18 ~{WE} (in) "Write Enable Input", 19 NC "No Connection", 20 A19 (in) "Address Input", 21 A18 (in) "Address Input", 22 A17 (in) "Address Input", 23 A16 (in) "Address Input", 24 A15 (in) "Address Input", 25 A14 (in) "Address Input", 26 A13 (in) "Address Input", 27 A12 (in) "Address Input", 28 A11 (in) "Address Input", 29 A10 (in) "Address Input", 30 A9 (in) "Address Input", 31 NC "No Connection", 32 I/O8 (io) "Data Input/Output", 33 I/O9 (io) "Data Input/Output", 34 I/O10 (io) "Data Input/Output", 35 I/O11 (io) "Data Input/Output", 36 VDD (power) "Power", 37 GND (power) "Ground", 38 I/O12 (io) "Data Input/Output", 39 I/O13 (io) "Data Input/Output", 40 I/O14 (io) "Data Input/Output", 41 I/O15 (io) "Data Input/Output", 42 ~{LB} (in) "Lower-byte Control (I/O0-I/O7)", 43 ~{UB} (in) "Upper-byte Control (I/O8-I/O15)", 44 ~{OE} (in) "Output Enable Input", 45 A8 (in) "Address Input", 46 A7 (in) "Address Input", 47 A6 (in) "Address Input", 48 A5 (in) "Address Input"

## IS62WV102416BLL-25TLI
designator U?
16 M High Speed Low Power Asynchronous CMOS SRAM, 1 M x 16, -40 to 85 degC, 48-Pin SOP (TSOP-1-48), Pb-Free; Manufacturer: Integrated Silicon Solution Inc (ISSI); PartNumber: IS62WV102416BLL-25TLI; Density: 16M; Organization: 1M x 16; Packing: Tray / Tube; Speed (ns): 25
footprint ISSI-TSOP-1-48-12000X20000DE_N (SOP, 48-Leads, Body 18.6x12.2mm, Pitch 0.5mm, IPC Medium Density)
pins: 1 A4 (in) "Address Input", 2 A3 (in) "Address Input", 3 A2 (in) "Address Input", 4 A1 (in) "Address Input", 5 A0 (in) "Address Input", 6 NC "No Connection", 7 ~{CE} (in) "Chip Enable Input", 8 I/O0 (io) "Data Input/Output", 9 I/O1 (io) "Data Input/Output", 10 I/O2 (io) "Data Input/Output", 11 I/O3 (io) "Data Input/Output", 12 VDD (power) "Power", 13 GND (power) "Ground", 14 I/O4 (io) "Data Input/Output", 15 I/O5 (io) "Data Input/Output", 16 I/O6 (io) "Data Input/Output", 17 I/O7 (io) "Data Input/Output", 18 ~{WE} (in) "Write Enable Input", 19 NC "No Connection", 20 A19 (in) "Address Input", 21 A18 (in) "Address Input", 22 A17 (in) "Address Input", 23 A16 (in) "Address Input", 24 A15 (in) "Address Input", 25 A14 (in) "Address Input", 26 A13 (in) "Address Input", 27 A12 (in) "Address Input", 28 A11 (in) "Address Input", 29 A10 (in) "Address Input", 30 A9 (in) "Address Input", 31 NC "No Connection", 32 I/O8 (io) "Data Input/Output", 33 I/O9 (io) "Data Input/Output", 34 I/O10 (io) "Data Input/Output", 35 I/O11 (io) "Data Input/Output", 36 VDD (power) "Power", 37 GND (power) "Ground", 38 I/O12 (io) "Data Input/Output", 39 I/O13 (io) "Data Input/Output", 40 I/O14 (io) "Data Input/Output", 41 I/O15 (io) "Data Input/Output", 42 ~{LB} (in) "Lower-byte Control (I/O0-I/O7)", 43 ~{UB} (in) "Upper-byte Control (I/O8-I/O15)", 44 ~{OE} (in) "Output Enable Input", 45 A8 (in) "Address Input", 46 A7 (in) "Address Input", 47 A6 (in) "Address Input", 48 A5 (in) "Address Input"

## IS62WV102416BLL-25TLI-TR
designator U?
16 M High Speed Low Power Asynchronous CMOS SRAM, 1 M x 16, -40 to 85 degC, 48-Pin SOP (TSOP-1-48), Pb-Free; Manufacturer: Integrated Silicon Solution Inc (ISSI); PartNumber: IS62WV102416BLL-25TLI-TR; Density: 16M; Organization: 1M x 16; Packing: Tape & Reel; Speed (ns): 25
footprint ISSI-TSOP-1-48-12000X20000DE_N (SOP, 48-Leads, Body 18.6x12.2mm, Pitch 0.5mm, IPC Medium Density)
pins: 1 A4 (in) "Address Input", 2 A3 (in) "Address Input", 3 A2 (in) "Address Input", 4 A1 (in) "Address Input", 5 A0 (in) "Address Input", 6 NC "No Connection", 7 ~{CE} (in) "Chip Enable Input", 8 I/O0 (io) "Data Input/Output", 9 I/O1 (io) "Data Input/Output", 10 I/O2 (io) "Data Input/Output", 11 I/O3 (io) "Data Input/Output", 12 VDD (power) "Power", 13 GND (power) "Ground", 14 I/O4 (io) "Data Input/Output", 15 I/O5 (io) "Data Input/Output", 16 I/O6 (io) "Data Input/Output", 17 I/O7 (io) "Data Input/Output", 18 ~{WE} (in) "Write Enable Input", 19 NC "No Connection", 20 A19 (in) "Address Input", 21 A18 (in) "Address Input", 22 A17 (in) "Address Input", 23 A16 (in) "Address Input", 24 A15 (in) "Address Input", 25 A14 (in) "Address Input", 26 A13 (in) "Address Input", 27 A12 (in) "Address Input", 28 A11 (in) "Address Input", 29 A10 (in) "Address Input", 30 A9 (in) "Address Input", 31 NC "No Connection", 32 I/O8 (io) "Data Input/Output", 33 I/O9 (io) "Data Input/Output", 34 I/O10 (io) "Data Input/Output", 35 I/O11 (io) "Data Input/Output", 36 VDD (power) "Power", 37 GND (power) "Ground", 38 I/O12 (io) "Data Input/Output", 39 I/O13 (io) "Data Input/Output", 40 I/O14 (io) "Data Input/Output", 41 I/O15 (io) "Data Input/Output", 42 ~{LB} (in) "Lower-byte Control (I/O0-I/O7)", 43 ~{UB} (in) "Upper-byte Control (I/O8-I/O15)", 44 ~{OE} (in) "Output Enable Input", 45 A8 (in) "Address Input", 46 A7 (in) "Address Input", 47 A6 (in) "Address Input", 48 A5 (in) "Address Input"

## IS63WV1288DBLL-8HI
designator U?
1 M High Speed CMOS SRAM, 128 K x 8, -40 to 85 degC, 32-Pin SOP (TSOP-1-32); Manufacturer: Integrated Silicon Solution Inc (ISSI); PartNumber: IS63WV1288DBLL-8HI; Organization: 128K x 8; Packing: Tray / Tube; Speed (ns): 8
footprint ISSI-TSOP-1-32-8000x13400DE_N (SOP, 32-Leads, Body 11.9x8.1mm, Pitch 0.5mm, IPC Medium Density)
pins: 1 A0 (in) "Address Input", 2 A1 (in) "Address Input", 3 A2 (in) "Address Input", 4 A3 (in) "Address Input", 5 ~{CE} (in) "Chip Enable Input", 6 I/O0 (io) "Bidirectional Port", 7 I/O1 (io) "Bidirectional Port", 8 VDD (power) "Power", 9 GND (power) "Ground", 10 I/O2 (io) "Bidirectional Port", 11 I/O3 (io) "Bidirectional Port", 12 ~{WE} (in) "Write Enable Input", 13 A4 (in) "Address Input", 14 A5 (in) "Address Input", 15 A6 (in) "Address Input", 16 A7 (in) "Address Input", 17 A8 (in) "Address Input", 18 A9 (in) "Address Input", 19 A10 (in) "Address Input", 20 A11 (in) "Address Input", 21 A12 (in) "Address Input", 22 I/O4 (io) "Bidirectional Port", 23 I/O5 (io) "Bidirectional Port", 24 VDD (power) "Power", 25 GND (power) "Ground", 26 I/O6 (io) "Bidirectional Port", 27 I/O7 (io) "Bidirectional Port", 28 ~{OE} (in) "Output Enable Input", 29 A13 (in) "Address Input", 30 A14 (in) "Address Input", 31 A15 (in) "Address Input", 32 A16 (in) "Address Input"

## IS63WV1288DBLL-8HI-TR
designator U?
1 M High Speed CMOS SRAM, 128 K x 8, -40 to 85 degC, 32-Pin SOP (TSOP-1-32); Manufacturer: Integrated Silicon Solution Inc (ISSI); PartNumber: IS63WV1288DBLL-8HI-TR; Organization: 128K x 8; Packing: Tape & Reel; Speed (ns): 8
footprint ISSI-TSOP-1-32-8000x13400DE_N (SOP, 32-Leads, Body 11.9x8.1mm, Pitch 0.5mm, IPC Medium Density)
pins: 1 A0 (in) "Address Input", 2 A1 (in) "Address Input", 3 A2 (in) "Address Input", 4 A3 (in) "Address Input", 5 ~{CE} (in) "Chip Enable Input", 6 I/O0 (io) "Bidirectional Port", 7 I/O1 (io) "Bidirectional Port", 8 VDD (power) "Power", 9 GND (power) "Ground", 10 I/O2 (io) "Bidirectional Port", 11 I/O3 (io) "Bidirectional Port", 12 ~{WE} (in) "Write Enable Input", 13 A4 (in) "Address Input", 14 A5 (in) "Address Input", 15 A6 (in) "Address Input", 16 A7 (in) "Address Input", 17 A8 (in) "Address Input", 18 A9 (in) "Address Input", 19 A10 (in) "Address Input", 20 A11 (in) "Address Input", 21 A12 (in) "Address Input", 22 I/O4 (io) "Bidirectional Port", 23 I/O5 (io) "Bidirectional Port", 24 VDD (power) "Power", 25 GND (power) "Ground", 26 I/O6 (io) "Bidirectional Port", 27 I/O7 (io) "Bidirectional Port", 28 ~{OE} (in) "Output Enable Input", 29 A13 (in) "Address Input", 30 A14 (in) "Address Input", 31 A15 (in) "Address Input", 32 A16 (in) "Address Input"

## IS63WV1288DBLL-8HLI
designator U?
1 M High Speed CMOS SRAM, 128 K x 8, -40 to 85 degC, 32-Pin SOP (TSOP-1-32), Pb-Free; Manufacturer: Integrated Silicon Solution Inc (ISSI); PartNumber: IS63WV1288DBLL-8HLI; Organization: 128K x 8; Packing: Tray / Tube; Speed (ns): 8
footprint ISSI-TSOP-1-32-8000x13400DE_N (SOP, 32-Leads, Body 11.9x8.1mm, Pitch 0.5mm, IPC Medium Density)
pins: 1 A0 (in) "Address Input", 2 A1 (in) "Address Input", 3 A2 (in) "Address Input", 4 A3 (in) "Address Input", 5 ~{CE} (in) "Chip Enable Input", 6 I/O0 (io) "Bidirectional Port", 7 I/O1 (io) "Bidirectional Port", 8 VDD (power) "Power", 9 GND (power) "Ground", 10 I/O2 (io) "Bidirectional Port", 11 I/O3 (io) "Bidirectional Port", 12 ~{WE} (in) "Write Enable Input", 13 A4 (in) "Address Input", 14 A5 (in) "Address Input", 15 A6 (in) "Address Input", 16 A7 (in) "Address Input", 17 A8 (in) "Address Input", 18 A9 (in) "Address Input", 19 A10 (in) "Address Input", 20 A11 (in) "Address Input", 21 A12 (in) "Address Input", 22 I/O4 (io) "Bidirectional Port", 23 I/O5 (io) "Bidirectional Port", 24 VDD (power) "Power", 25 GND (power) "Ground", 26 I/O6 (io) "Bidirectional Port", 27 I/O7 (io) "Bidirectional Port", 28 ~{OE} (in) "Output Enable Input", 29 A13 (in) "Address Input", 30 A14 (in) "Address Input", 31 A15 (in) "Address Input", 32 A16 (in) "Address Input"

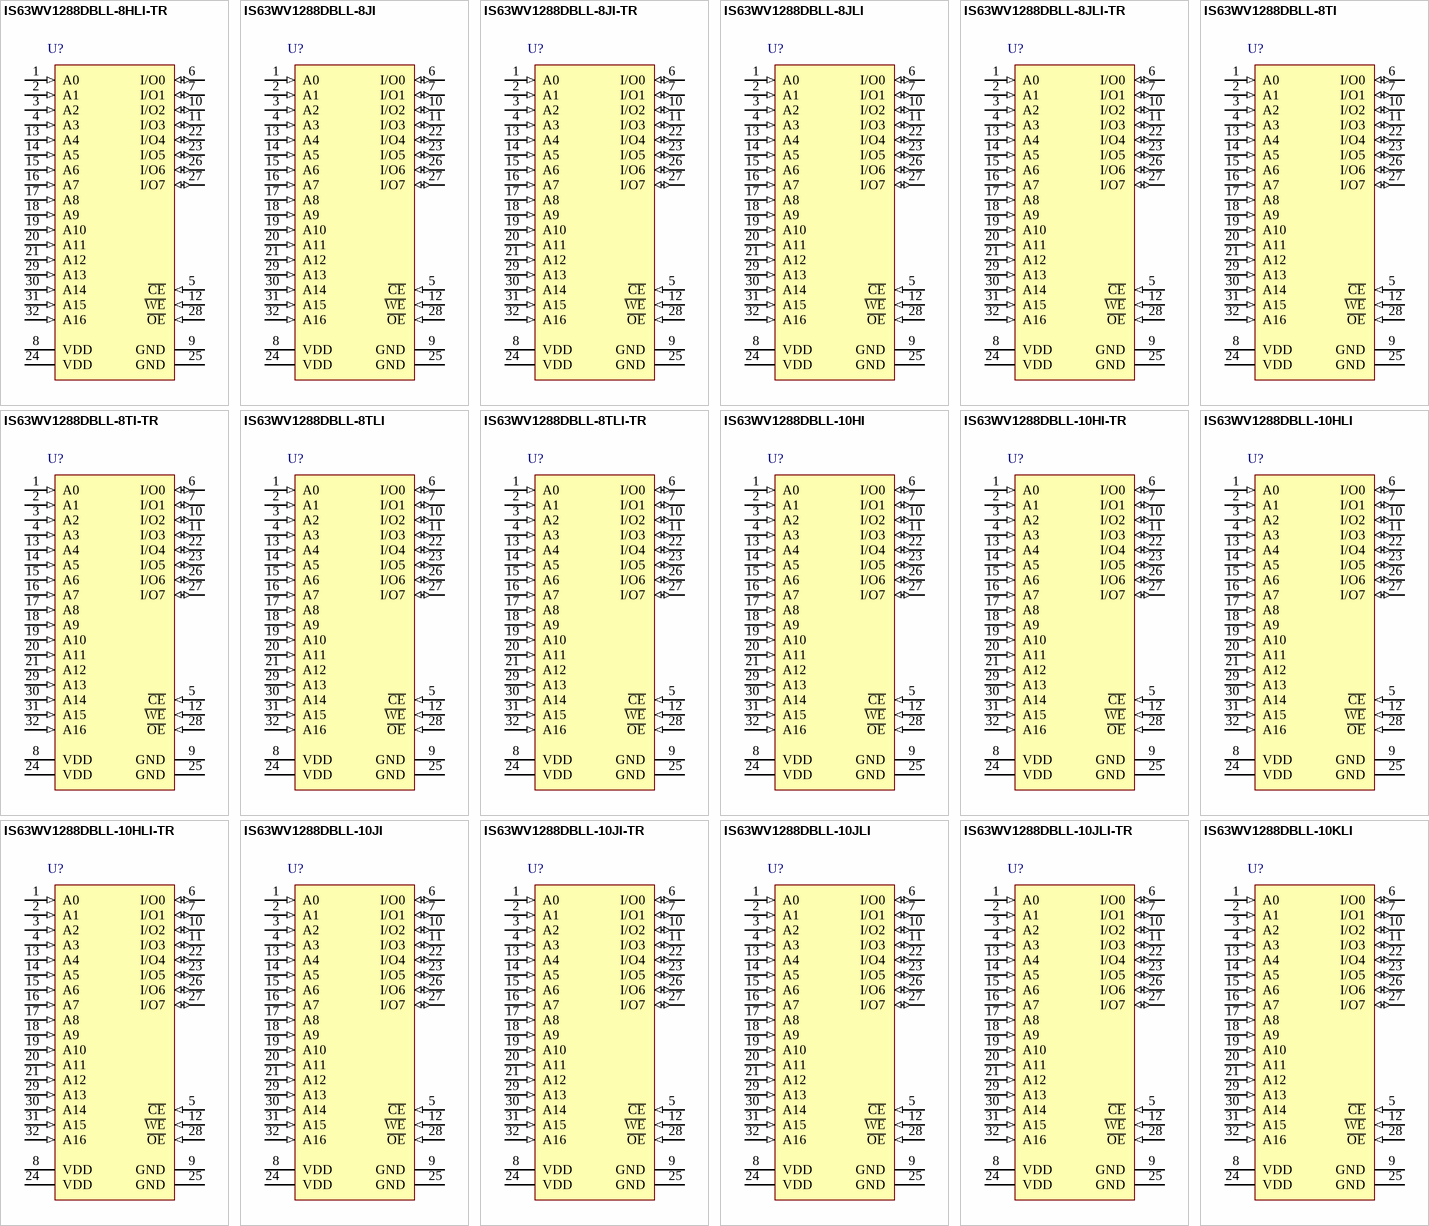
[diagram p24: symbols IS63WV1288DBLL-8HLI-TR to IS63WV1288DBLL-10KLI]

## IS63WV1288DBLL-8HLI-TR
designator U?
1 M High Speed CMOS SRAM, 128 K x 8, -40 to 85 degC, 32-Pin SOP (TSOP-1-32), Pb-Free; Manufacturer: Integrated Silicon Solution Inc (ISSI); PartNumber: IS63WV1288DBLL-8HLI-TR; Organization: 128K x 8; Packing: Tape & Reel; Speed (ns): 8
footprint ISSI-TSOP-1-32-8000x13400DE_N (SOP, 32-Leads, Body 11.9x8.1mm, Pitch 0.5mm, IPC Medium Density)
pins: 1 A0 (in) "Address Input", 2 A1 (in) "Address Input", 3 A2 (in) "Address Input", 4 A3 (in) "Address Input", 5 ~{CE} (in) "Chip Enable Input", 6 I/O0 (io) "Bidirectional Port", 7 I/O1 (io) "Bidirectional Port", 8 VDD (power) "Power", 9 GND (power) "Ground", 10 I/O2 (io) "Bidirectional Port", 11 I/O3 (io) "Bidirectional Port", 12 ~{WE} (in) "Write Enable Input", 13 A4 (in) "Address Input", 14 A5 (in) "Address Input", 15 A6 (in) "Address Input", 16 A7 (in) "Address Input", 17 A8 (in) "Address Input", 18 A9 (in) "Address Input", 19 A10 (in) "Address Input", 20 A11 (in) "Address Input", 21 A12 (in) "Address Input", 22 I/O4 (io) "Bidirectional Port", 23 I/O5 (io) "Bidirectional Port", 24 VDD (power) "Power", 25 GND (power) "Ground", 26 I/O6 (io) "Bidirectional Port", 27 I/O7 (io) "Bidirectional Port", 28 ~{OE} (in) "Output Enable Input", 29 A13 (in) "Address Input", 30 A14 (in) "Address Input", 31 A15 (in) "Address Input", 32 A16 (in) "Address Input"

## IS63WV1288DBLL-8JI
designator U?
1 M High Speed CMOS SRAM, 128 K x 8, -40 to 85 degC, 32-Pin SOJ (SOJ-32); Manufacturer: Integrated Silicon Solution Inc (ISSI); PartNumber: IS63WV1288DBLL-8JI; Organization: 128K x 8; Packing: Tray / Tube; Speed (ns): 8
footprint ISSI-SOJ-32_A_N (SOJ, 32-Leads, Body 21.09x7.75mm, Pitch 1.27mm, IPC Medium Density)
pins: 1 A0 (in) "Address Input", 2 A1 (in) "Address Input", 3 A2 (in) "Address Input", 4 A3 (in) "Address Input", 5 ~{CE} (in) "Chip Enable Input", 6 I/O0 (io) "Bidirectional Port", 7 I/O1 (io) "Bidirectional Port", 8 VDD (power) "Power", 9 GND (power) "Ground", 10 I/O2 (io) "Bidirectional Port", 11 I/O3 (io) "Bidirectional Port", 12 ~{WE} (in) "Write Enable Input", 13 A4 (in) "Address Input", 14 A5 (in) "Address Input", 15 A6 (in) "Address Input", 16 A7 (in) "Address Input", 17 A8 (in) "Address Input", 18 A9 (in) "Address Input", 19 A10 (in) "Address Input", 20 A11 (in) "Address Input", 21 A12 (in) "Address Input", 22 I/O4 (io) "Bidirectional Port", 23 I/O5 (io) "Bidirectional Port", 24 VDD (power) "Power", 25 GND (power) "Ground", 26 I/O6 (io) "Bidirectional Port", 27 I/O7 (io) "Bidirectional Port", 28 ~{OE} (in) "Output Enable Input", 29 A13 (in) "Address Input", 30 A14 (in) "Address Input", 31 A15 (in) "Address Input", 32 A16 (in) "Address Input"

## IS63WV1288DBLL-8JI-TR
designator U?
1 M High Speed CMOS SRAM, 128 K x 8, -40 to 85 degC, 32-Pin SOJ (SOJ-32_A); Manufacturer: Integrated Silicon Solution Inc (ISSI); PartNumber: IS63WV1288DBLL-8JI-TR; Organization: 128K x 8; Packing: Tape & Reel; Speed (ns): 8
footprint ISSI-SOJ-32_A_N (SOJ, 32-Leads, Body 21.09x7.75mm, Pitch 1.27mm, IPC Medium Density)
pins: 1 A0 (in) "Address Input", 2 A1 (in) "Address Input", 3 A2 (in) "Address Input", 4 A3 (in) "Address Input", 5 ~{CE} (in) "Chip Enable Input", 6 I/O0 (io) "Bidirectional Port", 7 I/O1 (io) "Bidirectional Port", 8 VDD (power) "Power", 9 GND (power) "Ground", 10 I/O2 (io) "Bidirectional Port", 11 I/O3 (io) "Bidirectional Port", 12 ~{WE} (in) "Write Enable Input", 13 A4 (in) "Address Input", 14 A5 (in) "Address Input", 15 A6 (in) "Address Input", 16 A7 (in) "Address Input", 17 A8 (in) "Address Input", 18 A9 (in) "Address Input", 19 A10 (in) "Address Input", 20 A11 (in) "Address Input", 21 A12 (in) "Address Input", 22 I/O4 (io) "Bidirectional Port", 23 I/O5 (io) "Bidirectional Port", 24 VDD (power) "Power", 25 GND (power) "Ground", 26 I/O6 (io) "Bidirectional Port", 27 I/O7 (io) "Bidirectional Port", 28 ~{OE} (in) "Output Enable Input", 29 A13 (in) "Address Input", 30 A14 (in) "Address Input", 31 A15 (in) "Address Input", 32 A16 (in) "Address Input"

## IS63WV1288DBLL-8JLI
designator U?
1 M High Speed CMOS SRAM, 128 K x 8, -40 to 85 degC, 32-Pin SOJ (SOJ-32), Pb-Free; Manufacturer: Integrated Silicon Solution Inc (ISSI); PartNumber: IS63WV1288DBLL-8JLI; Organization: 128K x 8; Packing: Tray / Tube; Speed (ns): 8
footprint ISSI-SOJ-32_A_N (SOJ, 32-Leads, Body 21.09x7.75mm, Pitch 1.27mm, IPC Medium Density)
pins: 1 A0 (in) "Address Input", 2 A1 (in) "Address Input", 3 A2 (in) "Address Input", 4 A3 (in) "Address Input", 5 ~{CE} (in) "Chip Enable Input", 6 I/O0 (io) "Bidirectional Port", 7 I/O1 (io) "Bidirectional Port", 8 VDD (power) "Power", 9 GND (power) "Ground", 10 I/O2 (io) "Bidirectional Port", 11 I/O3 (io) "Bidirectional Port", 12 ~{WE} (in) "Write Enable Input", 13 A4 (in) "Address Input", 14 A5 (in) "Address Input", 15 A6 (in) "Address Input", 16 A7 (in) "Address Input", 17 A8 (in) "Address Input", 18 A9 (in) "Address Input", 19 A10 (in) "Address Input", 20 A11 (in) "Address Input", 21 A12 (in) "Address Input", 22 I/O4 (io) "Bidirectional Port", 23 I/O5 (io) "Bidirectional Port", 24 VDD (power) "Power", 25 GND (power) "Ground", 26 I/O6 (io) "Bidirectional Port", 27 I/O7 (io) "Bidirectional Port", 28 ~{OE} (in) "Output Enable Input", 29 A13 (in) "Address Input", 30 A14 (in) "Address Input", 31 A15 (in) "Address Input", 32 A16 (in) "Address Input"

## IS63WV1288DBLL-8JLI-TR
designator U?
1 M High Speed CMOS SRAM, 128 K x 8, -40 to 85 degC, 32-Pin SOJ (SOJ-32_A), Pb-Free; Manufacturer: Integrated Silicon Solution Inc (ISSI); PartNumber: IS63WV1288DBLL-8JLI-TR; Organization: 128K x 8; Packing: Tape & Reel; Speed (ns): 8
footprint ISSI-SOJ-32_A_N (SOJ, 32-Leads, Body 21.09x7.75mm, Pitch 1.27mm, IPC Medium Density)
pins: 1 A0 (in) "Address Input", 2 A1 (in) "Address Input", 3 A2 (in) "Address Input", 4 A3 (in) "Address Input", 5 ~{CE} (in) "Chip Enable Input", 6 I/O0 (io) "Bidirectional Port", 7 I/O1 (io) "Bidirectional Port", 8 VDD (power) "Power", 9 GND (power) "Ground", 10 I/O2 (io) "Bidirectional Port", 11 I/O3 (io) "Bidirectional Port", 12 ~{WE} (in) "Write Enable Input", 13 A4 (in) "Address Input", 14 A5 (in) "Address Input", 15 A6 (in) "Address Input", 16 A7 (in) "Address Input", 17 A8 (in) "Address Input", 18 A9 (in) "Address Input", 19 A10 (in) "Address Input", 20 A11 (in) "Address Input", 21 A12 (in) "Address Input", 22 I/O4 (io) "Bidirectional Port", 23 I/O5 (io) "Bidirectional Port", 24 VDD (power) "Power", 25 GND (power) "Ground", 26 I/O6 (io) "Bidirectional Port", 27 I/O7 (io) "Bidirectional Port", 28 ~{OE} (in) "Output Enable Input", 29 A13 (in) "Address Input", 30 A14 (in) "Address Input", 31 A15 (in) "Address Input", 32 A16 (in) "Address Input"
